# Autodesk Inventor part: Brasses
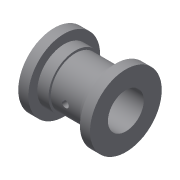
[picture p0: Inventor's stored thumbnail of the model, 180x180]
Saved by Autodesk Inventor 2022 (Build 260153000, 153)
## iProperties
Created: 2009-04
Part Number: Brasses
Document SubType Name: Modeling
Designer: Sham
Density: 1 g/cm^3
Material: Generic
Appearance: Default
Author: Sham
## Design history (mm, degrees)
sketch "Sketch1"
  geometry: L1 (0, 32)-(9, 32); L2 (0, 16)-(64, 16); L3 (64, 32)-(55, 32); L4 (55, 32)-(55, 24); L5 (55, 24)-(47, 24); L6 (19, 22)-(47, 22); L7 (47, 24)-(47, 22); L8 (19, 22)-(19, 24); L9 (19, 24)-(9, 24); L10 (9, 24)-(9, 32); L11 (0, 32)-(0, 16); L12 (64, 32)-(64, 16); L13 (-12.8, 0)-(76.8, 0) reference; 1 further point
  constraints: 24 end point, 7 parallel, 4 perpendicular, 1 collinear, 1 horizontal, 1 vertical alignment, 1 other
  dimensions: "d0" = 9 distance of L1.start L1.end; "d2" = 16 distance from line of L2 point (0, 0); "d3" = 64 distance of L2.start L2.end; "d4" = 24 distance from line of point (0, 0) L5; "d5" = 28 distance of L6.start L6.end; "d6" = 22 distance from line of point (0, 0) L6; "d7" = 8 distance of L4.end L5.end
revolve "Revolution1" sketch "Sketch1" stored, may be unused: angle "d8" = 90 deg
workplane "Work Plane1"
sketch "Sketch2"
  geometry: C1 r 4 at (-32, 0)
  constraints: 1 centre point
  dimensions: "d10" = 8 diameter of C1
extrude "Extrusion1" join sketch "Sketch2" stored distance "d11" = 10; taper "d12" = 0 deg
sketch "Sketch3"
  geometry: C1 r 4 at (0, 0) reference; C2 r 3 at (0, 0)
  constraints: 1 centre point, 1 coincident
  dimensions: "d13" = 6 diameter of C2
extrude "Extrusion2" cut sketch "Sketch3" extent not by distance; stored distance "d14" = 10; taper "d15" = 0 deg
body "Solid1"
